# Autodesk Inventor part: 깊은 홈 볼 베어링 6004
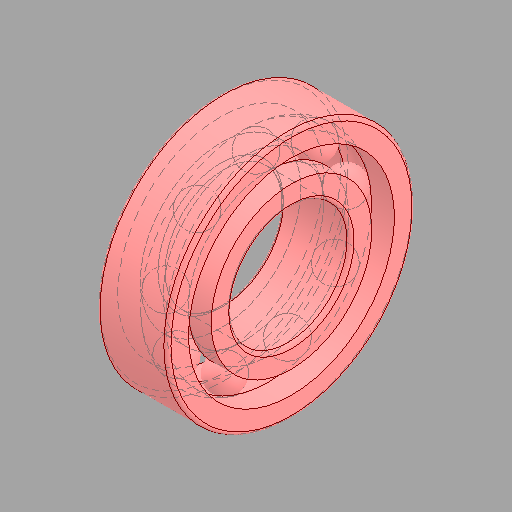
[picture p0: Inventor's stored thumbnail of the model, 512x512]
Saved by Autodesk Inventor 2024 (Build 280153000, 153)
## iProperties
Created: 2025-11
Part Number: 깊은 홈 볼 베어링 6004
Material: 강철, 연강
Description: 깊은 그루브 볼 베어링
Document SubType Name: Modeling
Designer: Edu09
Density: 7.85 g/cm^3
Appearance: 기본값
Author: jhkim
Sending System: Autodesk Inventor 2026
Preprocessor: ST-DEVELOPER v20.1
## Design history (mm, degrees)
feature "Solid1"
feature "Solid1:1"
feature "Solid1:2"
feature "Solid1:3"
feature "Solid1:4"
feature "Solid1:5"
feature "Solid1:6"
feature "Solid1:7"
feature "Solid1:8"
feature "Solid1:9"
feature "Solid1:10"
node "솔리드1"
node "솔리드2"
node "솔리드3"
node "솔리드4"
node "솔리드5"
node "솔리드6"
node "솔리드7"
node "솔리드8"
node "솔리드9"
node "솔리드10"
node "솔리드11"
